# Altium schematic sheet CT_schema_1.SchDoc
size 389 x 342 mm
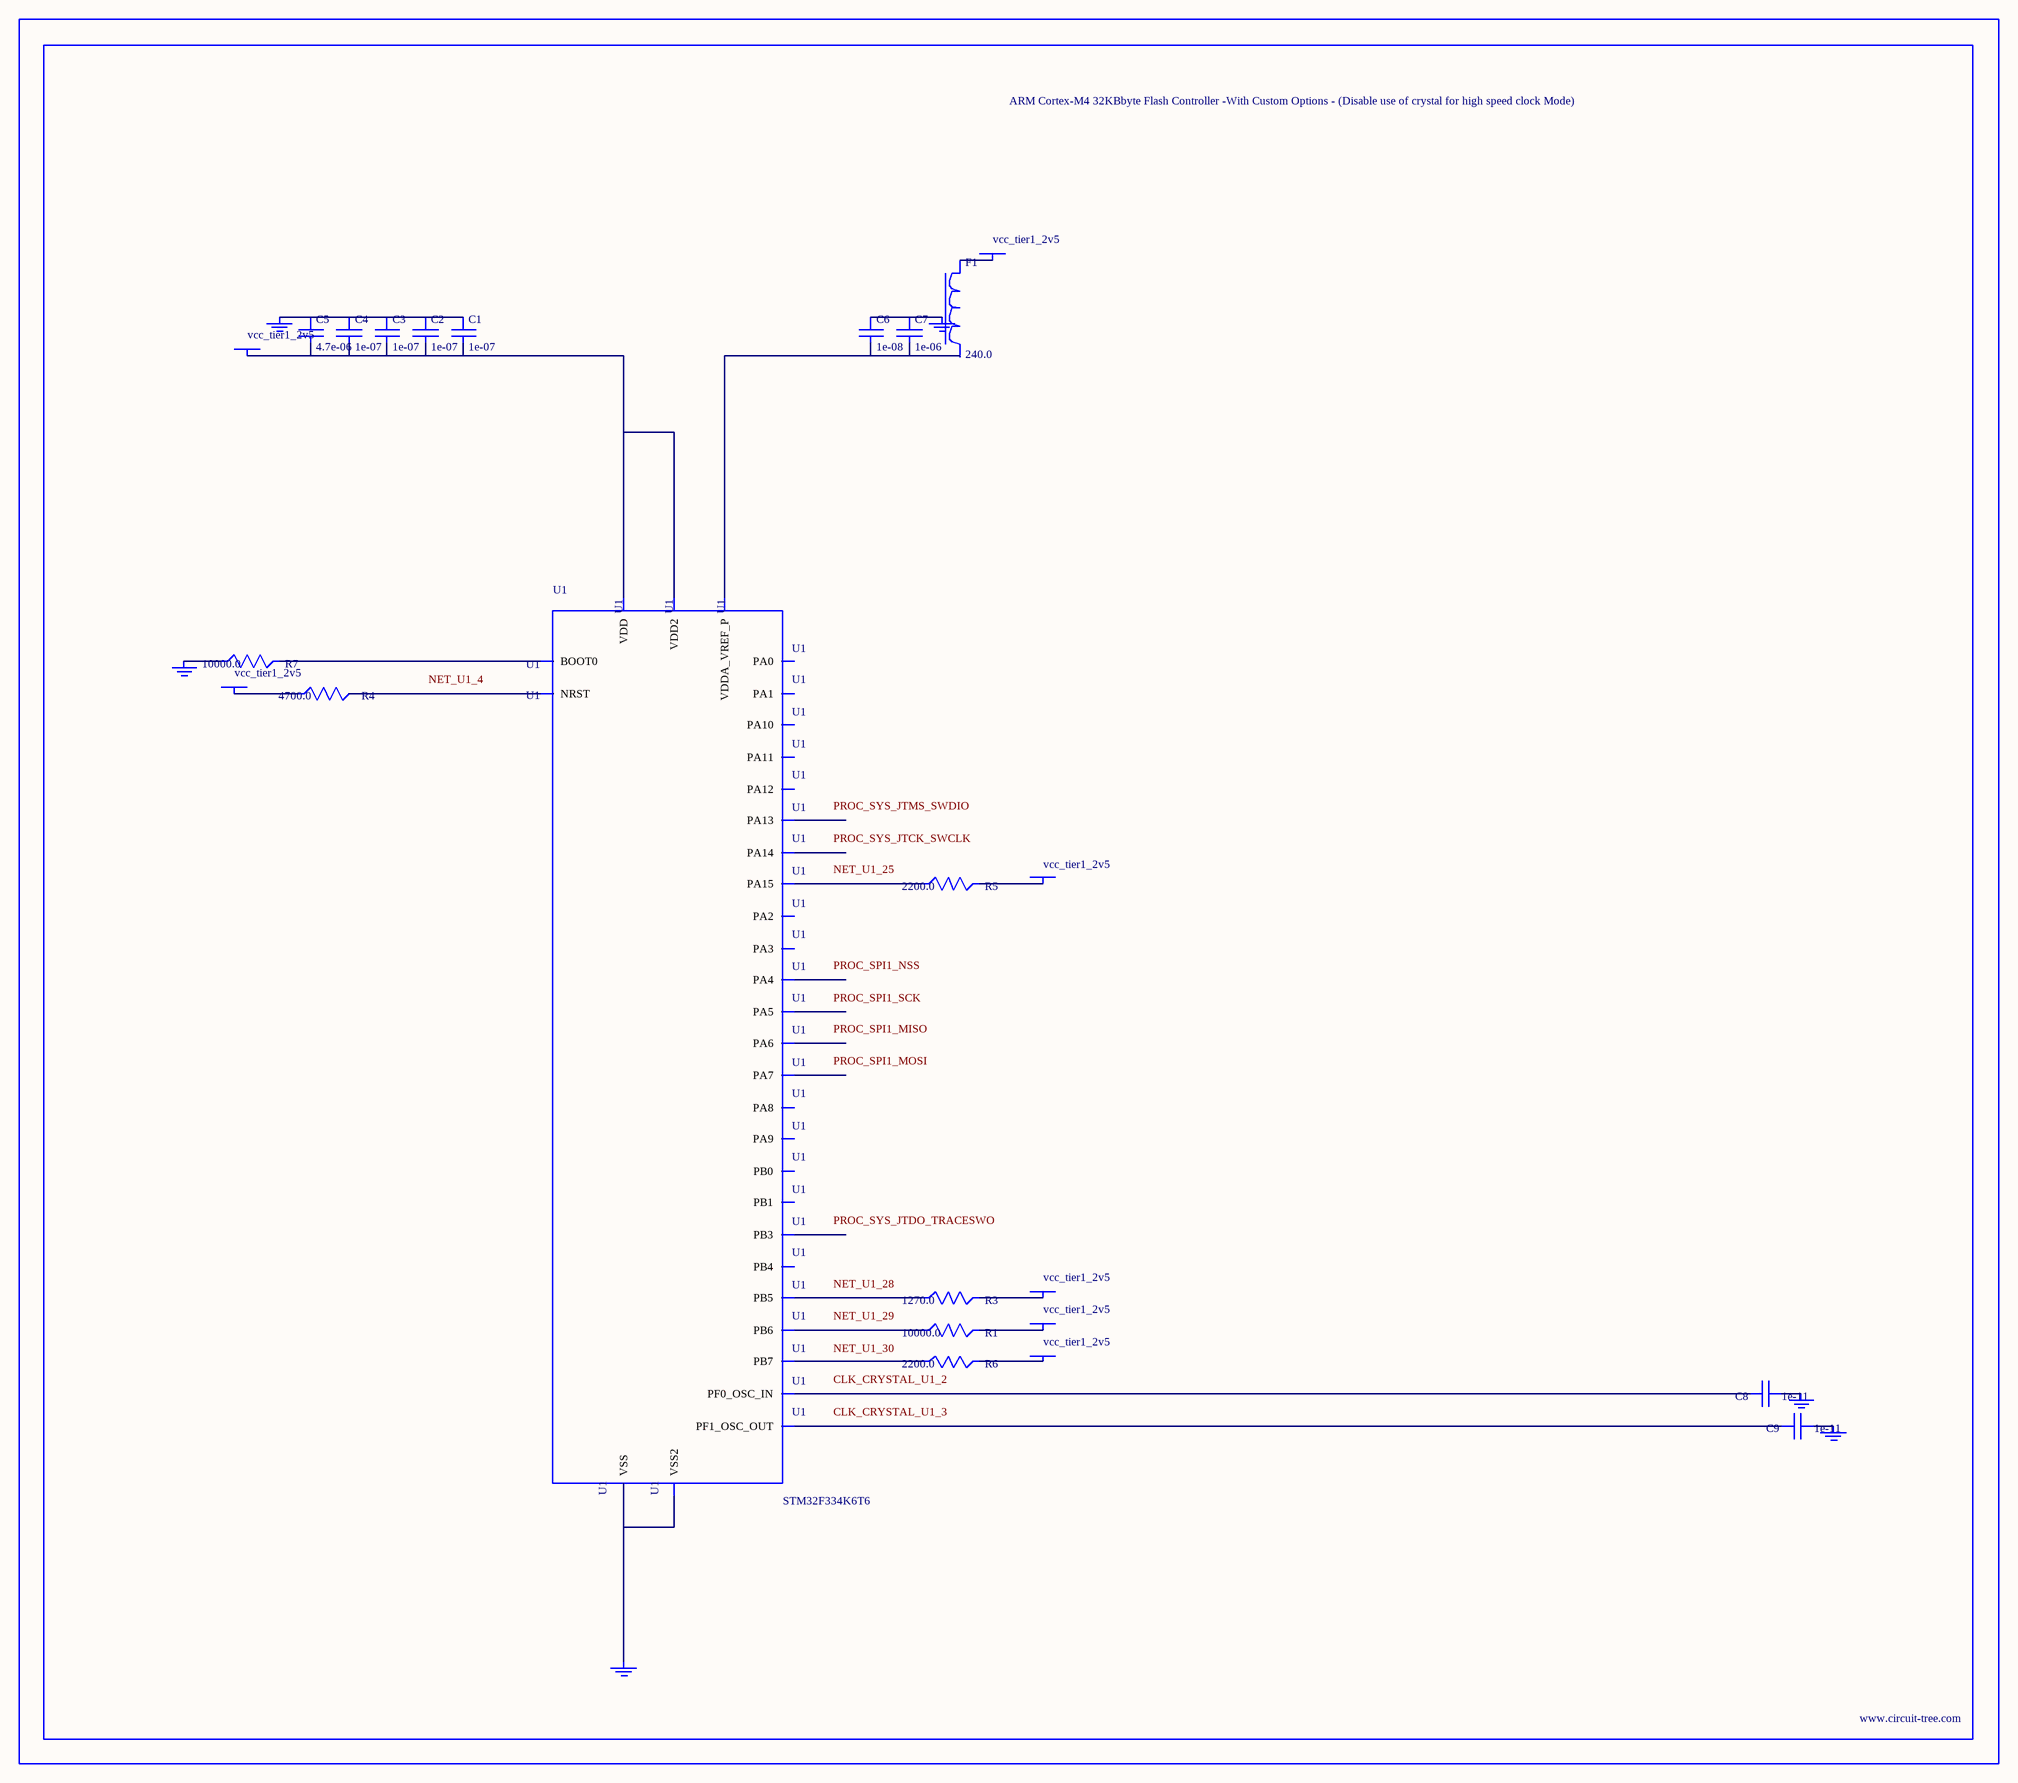
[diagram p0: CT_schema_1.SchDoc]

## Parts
BORDER0  (no value)
C1  1e-07  [C0603]
C2  1e-07  [C0603]
C3  1e-07  [C0603]
C4  1e-07  [C0603]
C5  4.7e-06  [C0603]
C6  1e-08  [C0603]
C7  1e-06  [C0603]
C8  1e-11  [C0402]
C9  1e-11  [C0402]
F1  240.0  [L0603]
GND_INSTANCE_0_0  (no value)
GND_INSTANCE_0_1  (no value)
GND_INSTANCE_0_2  (no value)
GND_INSTANCE_0_3  (no value)
GND_INSTANCE_0_4  (no value)
GND_INSTANCE_0_5  (no value)
POWER_INSTANCE_0_0  vcc_tier1_2v5
POWER_INSTANCE_0_1  vcc_tier1_2v5
POWER_INSTANCE_0_2  vcc_tier1_2v5
POWER_INSTANCE_0_3  vcc_tier1_2v5
POWER_INSTANCE_0_4  vcc_tier1_2v5
POWER_INSTANCE_0_5  vcc_tier1_2v5
POWER_INSTANCE_0_6  vcc_tier1_2v5
R1  10000.0  [R0603]
R3  1270.0  [R0603]
R4  4700.0  [R0603]
R5  2200.0  [R0603]
R6  2200.0  [R0603]
R7  10000.0  [R0603]
U1  STM32F334K6T6  [LQFP32]

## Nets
NetC1_1: C1.1 C2.1 C3.1 C4.1 C5.1 GND_INSTANCE_0_0.0(GND)
NetC1_2: C1.2 C2.2 C3.2 C4.2 C5.2 POWER_INSTANCE_0_0.0(PWR) U1.1(VDD) U1.17(VDD2)
NetC6_1: C6.1 C7.1 GND_INSTANCE_0_3.0(GND)
NetC6_2: C6.2 C7.2 U1.5(VDDA_VREF_P)
NetC8_1: C8.1 GND_INSTANCE_0_1.0(GND)
NetC8_2: C8.2 U1.2(PF0_OSC_IN)
NetC9_1: C9.1 GND_INSTANCE_0_2.0(GND)
NetC9_2: C9.2 U1.3(PF1_OSC_OUT)
NetF1_1: F1.1 POWER_INSTANCE_0_1.0(PWR)
NetGND_INSTANCE_0_4_0: GND_INSTANCE_0_4.0(GND) R7.1
NetGND_INSTANCE_0_5_0: GND_INSTANCE_0_5.0(GND) U1.16(VSS) U1.32(VSS2)
NetPOWER_INSTANCE_0_2_0: POWER_INSTANCE_0_2.0(PWR) R4.1
NetPOWER_INSTANCE_0_3_0: POWER_INSTANCE_0_3.0(PWR) R5.2
NetPOWER_INSTANCE_0_4_0: POWER_INSTANCE_0_4.0(PWR) R3.2
NetPOWER_INSTANCE_0_5_0: POWER_INSTANCE_0_5.0(PWR) R1.2
NetPOWER_INSTANCE_0_6_0: POWER_INSTANCE_0_6.0(PWR) R6.2
NetR1_1: R1.1 U1.29(PB6)
NetR3_1: R3.1 U1.28(PB5)
NetR4_2: R4.2 U1.4(NRST)
NetR5_1: R5.1 U1.25(PA15)
NetR6_1: R6.1 U1.30(PB7)
NetR7_2: R7.2 U1.31(BOOT0)

Not connected (* = marked no-connect by the designer): F1 2; U1 6(PA0) 7(PA1) 8(PA2) 9(PA3) 10(PA4) 11(PA5) 12(PA6) 13(PA7) 14(PB0) 15(PB1) 18(PA8) 19(PA9) 20(PA10) 21(PA11) 22(PA12) 23(PA13) 24(PA14) 26(PB3) 27(PB4)

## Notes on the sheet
- Labels drawn without touching a wire or pin: CLK_CRYSTAL_U1_2, CLK_CRYSTAL_U1_3, NET_U1_4, NET_U1_25, NET_U1_28, NET_U1_29, NET_U1_30, PROC_SPI1_MISO, PROC_SPI1_MOSI, PROC_SPI1_NSS, PROC_SPI1_SCK, PROC_SYS_JTCK_SWCLK, PROC_SYS_JTDO_TRACESWO, PROC_SYS_JTMS_SWDIO

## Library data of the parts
BORDER0 = BORDER_PAGE0
C1-C4 = 06035C104K4Z2A
C5 = GRM188R6YA475KE15D
C6 = 06035C103K4Z2A
C7 = C0603C105K3RACTU
C8 C9 = C0402C100K3GACTU
F1 = Z0603C241ASMST
GND_INSTANCE_0_0-GND_INSTANCE_0_5 = GND
POWER_INSTANCE_0_0-POWER_INSTANCE_0_6 = PWR
R1 R7 = RC0603JR-0710KL
R3 = RC0603FR-071K27L
R4 = RC0603JR-074K7L
R5 R6 = RC0603JR-072K2L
